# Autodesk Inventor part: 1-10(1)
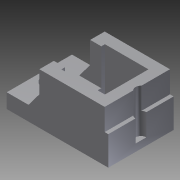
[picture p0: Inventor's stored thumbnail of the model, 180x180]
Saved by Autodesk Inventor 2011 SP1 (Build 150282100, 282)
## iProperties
Created: 2014-02
Part Number: 1-10(1)
Document SubType Name: Modeling
Designer: Administrator
Density: 1 g/cm^3
Author: Administrator
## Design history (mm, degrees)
sketch "草图1"
  geometry: L1 (-14, 9)-(14, 9); L2 (14, 9)-(14, -9); L3 (14, -9)-(-14, -9); L4 (-14, -9)-(-14, 9); 3 further points
  constraints: 8 end point, 2 midpoint, 2 parallel, 1 horizontal, 1 horizontal alignment, 1 perpendicular, 1 vertical alignment
extrude "拉伸1" new body sketch "草图1" distance "d0" = 4; taper "d1" = 0 deg
sketch "草图2"
  geometry: L1 (28, 4)-(0, 4) reference; L2 (0, 4)-(6, 4); L3 (6, 4)-(9, 8); L4 (9, 8)-(9, 14); L5 (9, 14)-(28, 14); L6 (28, 14)-(28, 4); 1 further point
  constraints: 10 end point, 3 perpendicular, 1 point on line
extrude "拉伸2" join sketch "草图2" distance "d2" = 4; taper "d3" = 0 deg
mirror "镜像1"
sketch "草图3"
  geometry: L1 (-8, -5)-(14, -5) reference; L2 (14, 5)-(14, -5) reference; L3 (14, 5)-(-8, 5) reference; L4 (14, 5)-(10, 5); L5 (10, -5)-(14, -5); L6 (10, -5)-(10, 5); L7 (14, 5)-(14, -5); 1 further point
  constraints: 8 end point, 2 collinear, 2 point on line, 1 perpendicular
extrude "拉伸3" join sketch "草图3" stored distance "d4" = 4; taper "d5" = 0 deg
sketch "草图4"
  geometry: C1 r 3 at (-10, 0); 1 further point
  constraints: 1 centre point
  dimensions: "d6" = 6 diameter of C1
extrude "拉伸4" cut sketch "草图4" stored distance "d7" = 4; taper "d8" = 0 deg
sketch "草图5"
  geometry: L1 (-10.064, -6)-(1.936, -6); L2 (1.936, -6)-(1.936, 6); L3 (1.936, 6)-(-10.064, 6); L4 (-10.064, 6)-(-10.064, -6); 4 further points
  constraints: 8 end point, 3 midpoint, 2 parallel, 1 horizontal, 1 horizontal alignment, 1 perpendicular
  dimensions: "d11" = 12 distance of L1.end L2.end; "d12" = 12 distance of L1.start L1.end
extrude "拉伸5" cut sketch "草图5" stored distance "d9" = 4; taper "d10" = 0 deg
sketch "草图6"
  geometry: L1 (19, 0)-(0, 0) reference; L2 (19, 18)-(19, 0) reference; L3 (19, 18)-(0, 18) reference; L4 (19, 0)-(18, 0); L5 (18, 0)-(18, 18); L6 (18, 18)-(19, 18); L7 (19, 0)-(19, 18); 1 further point
  constraints: 8 end point, 2 perpendicular, 2 point on line, 1 collinear
  dimensions: "d13" = 1 distance of L1.start L4.end
extrude "拉伸6" cut sketch "草图6" distance "d14" = 6; taper "d15" = 0 deg
sketch "草图7"
  geometry: L1 (19, 18)-(19, 0) reference; A1 r 1.5 centre (19, 9) between (19, 10.5) and (19, 7.5); 1 further point
  constraints: 2 point on circle, 2 point on line, 1 centre point, 1 midpoint
  dimensions: "d17" = 3 diameter of A1
extrude "拉伸7" cut sketch "草图7" distance "d18" = 12; taper "d19" = 0 deg
node "实体1"
